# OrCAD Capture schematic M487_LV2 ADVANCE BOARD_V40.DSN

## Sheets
1 EBI_SRAM: size A; title: SRAM; rev: V4.0; note: NuMaker M487 Advance (LV2)
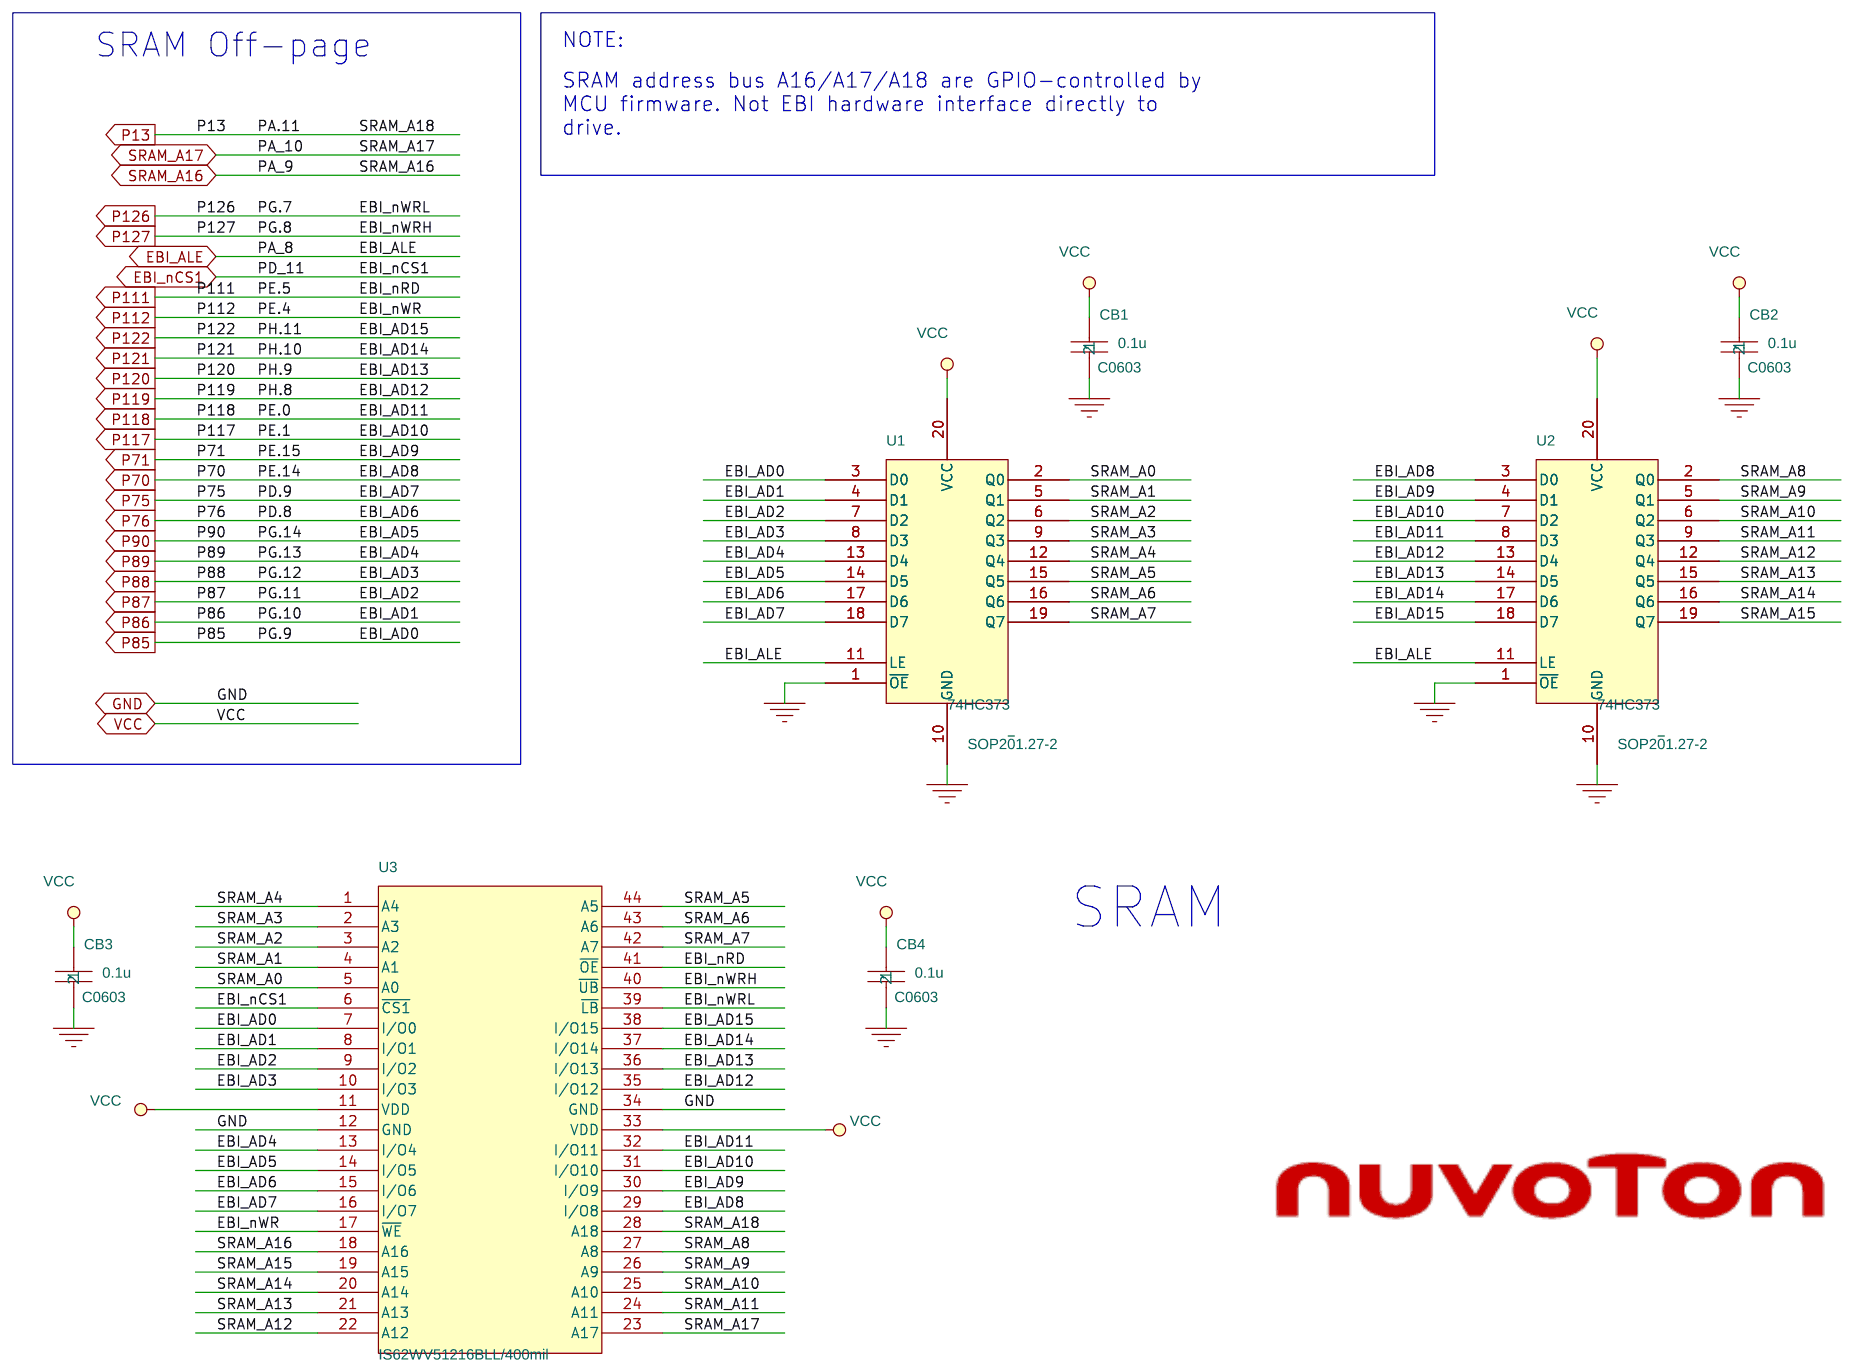
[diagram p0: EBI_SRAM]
2 EBI_TFT LCD: size A4; title: TFT LCD Module
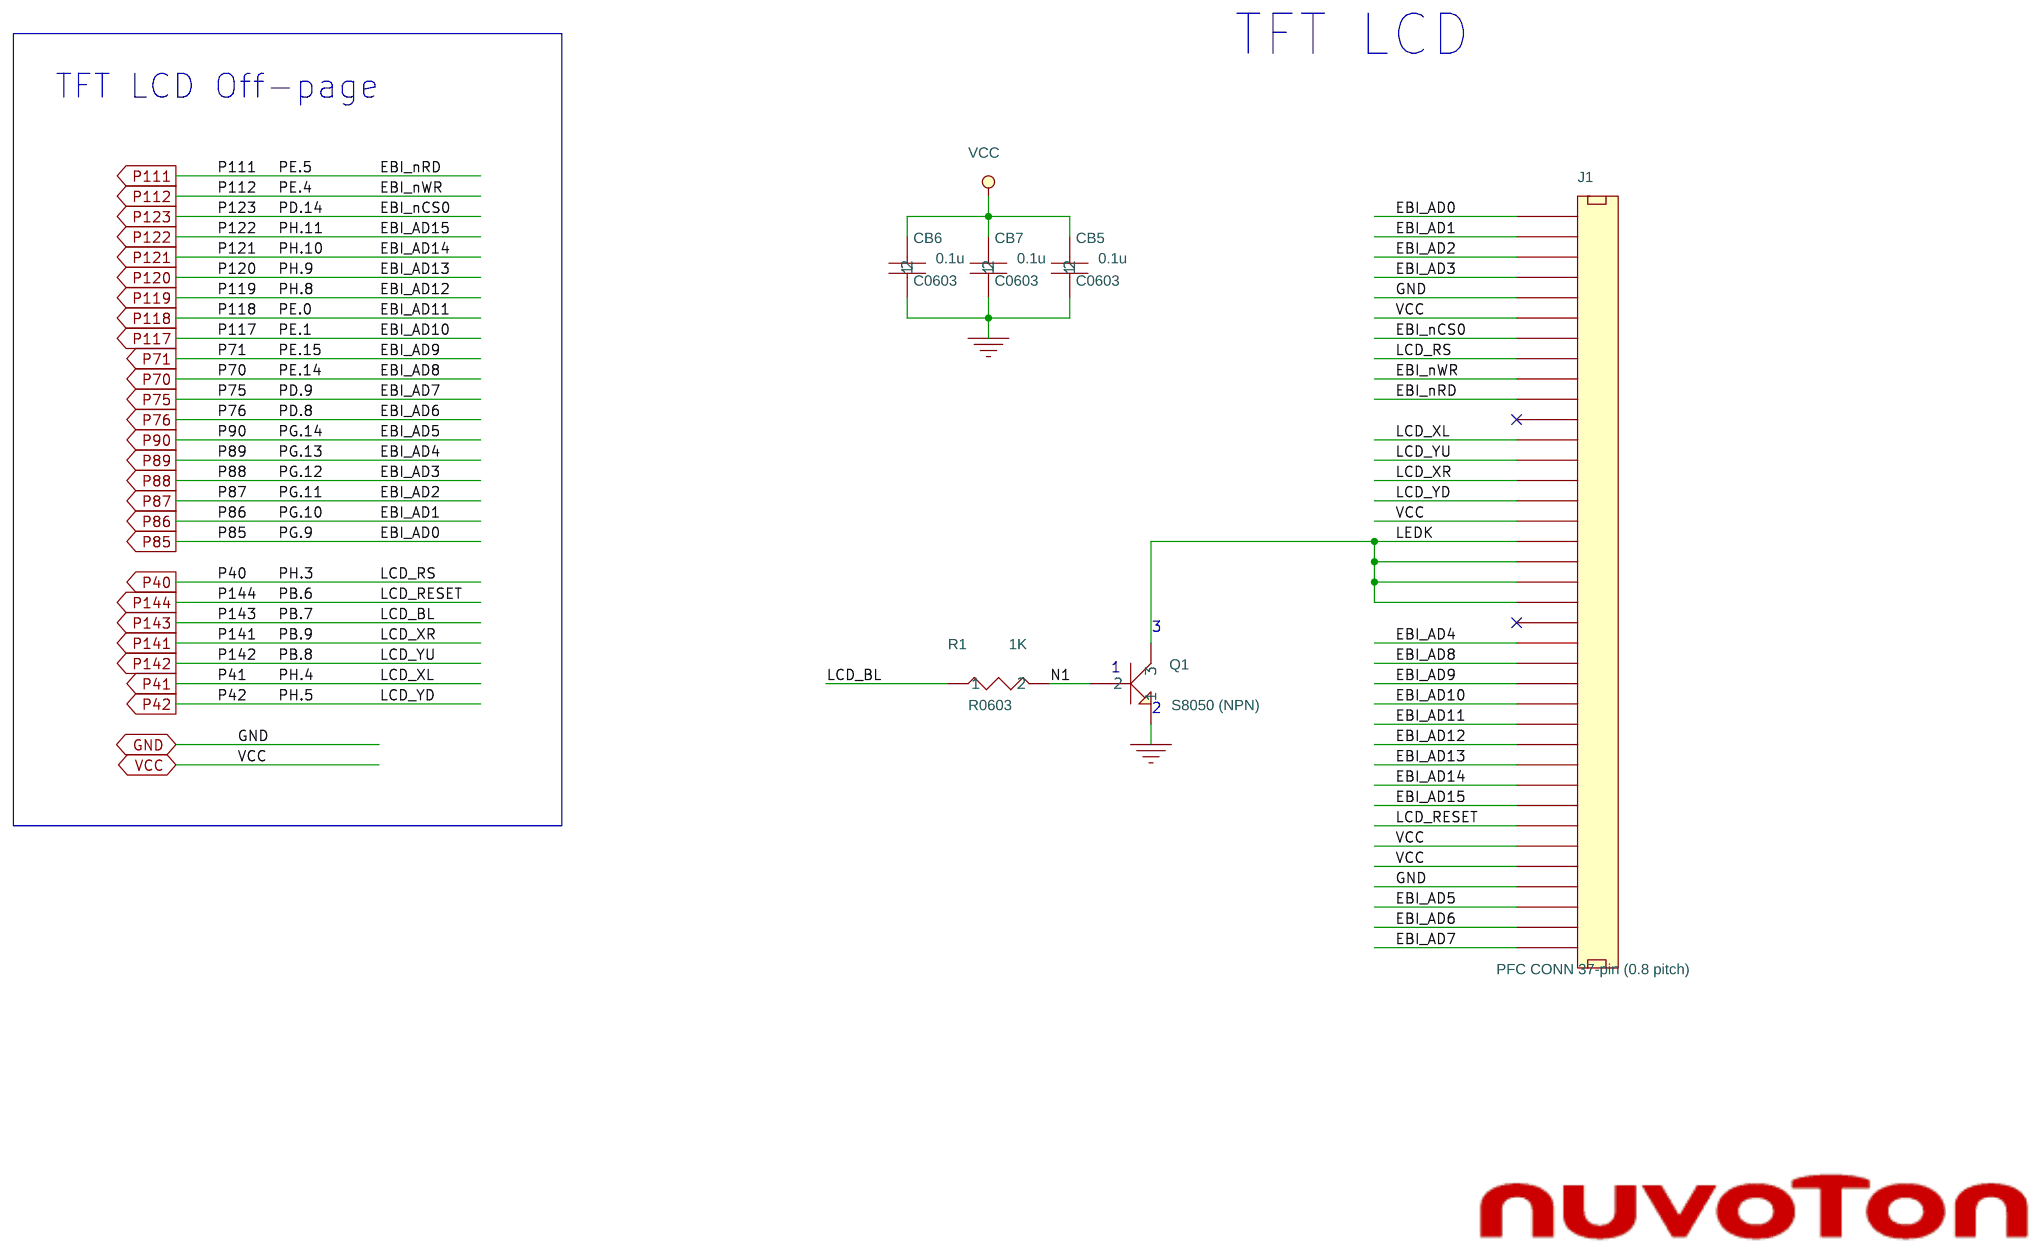
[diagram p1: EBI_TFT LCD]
3 I2C_EEPROM (24LC64): size A; title: I2C EEPROM
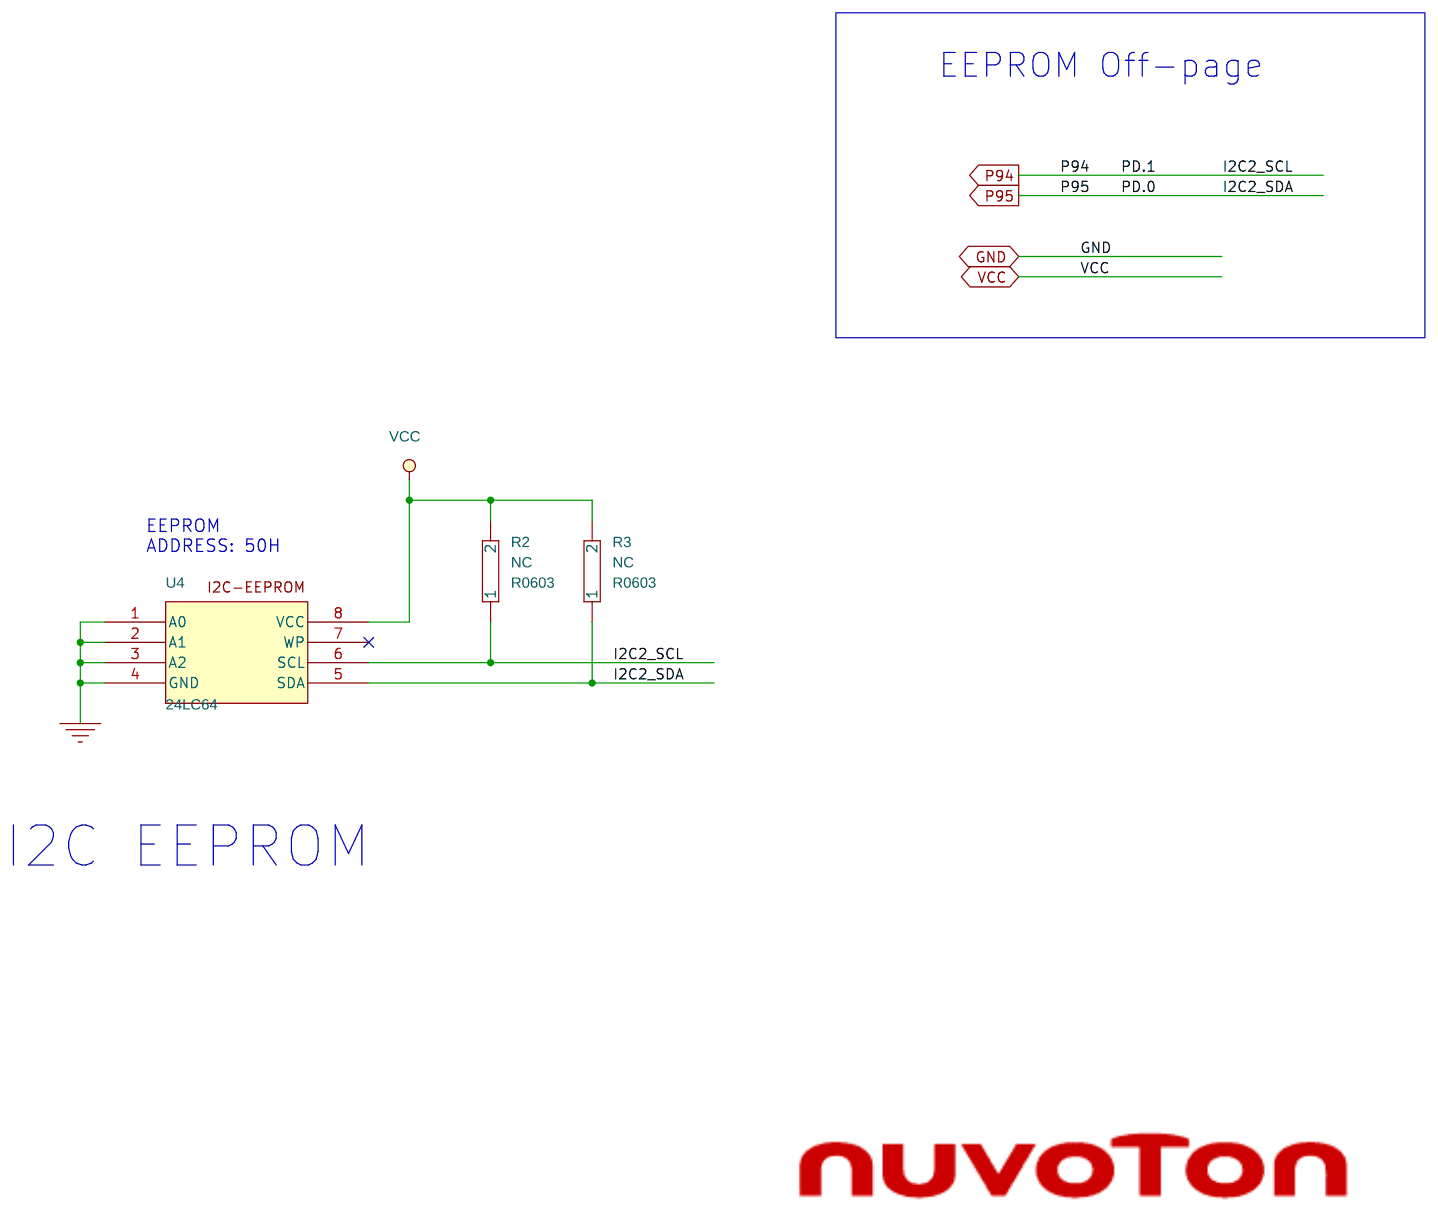
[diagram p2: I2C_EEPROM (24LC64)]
4 I2C_MEMS (MPU6500): size A; title: MEMS (MPU6500)
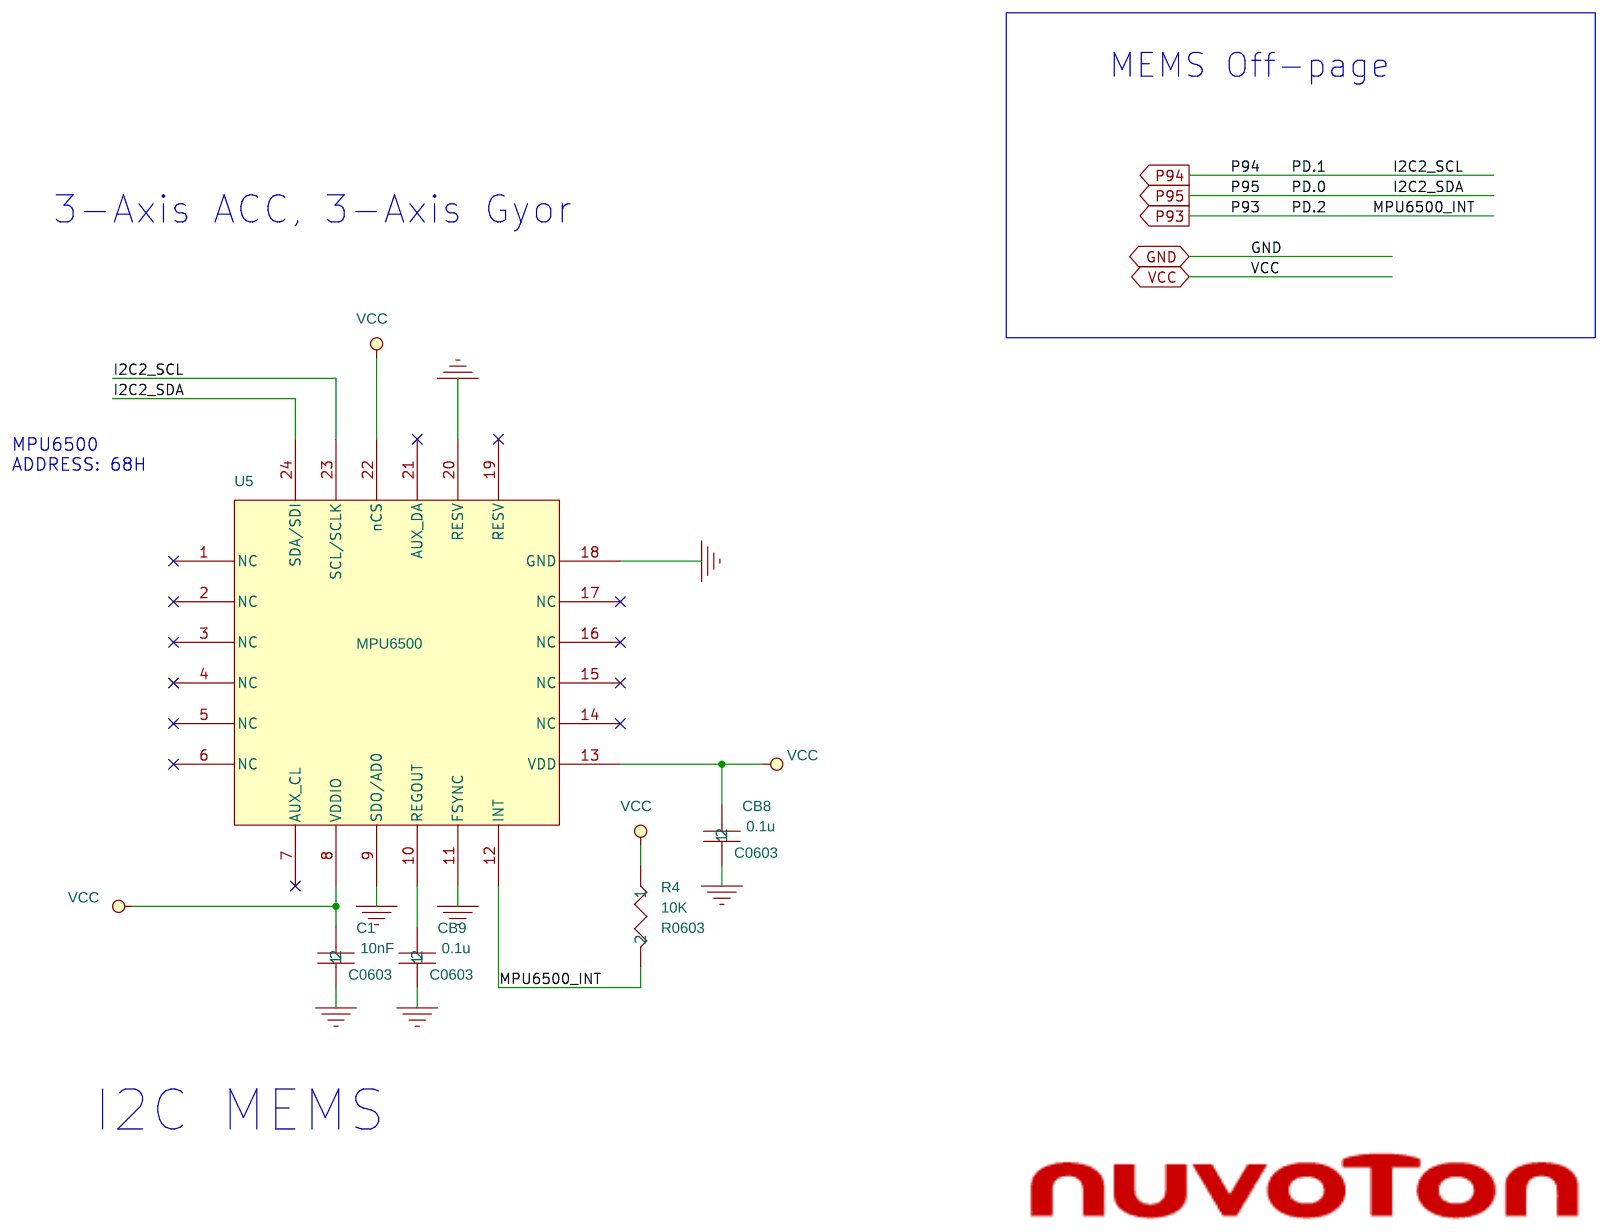
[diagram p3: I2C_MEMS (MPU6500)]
5 Joystick & LED & Keys & Buzzer: size A; title: Joystick, LED, Keys and Buzzer
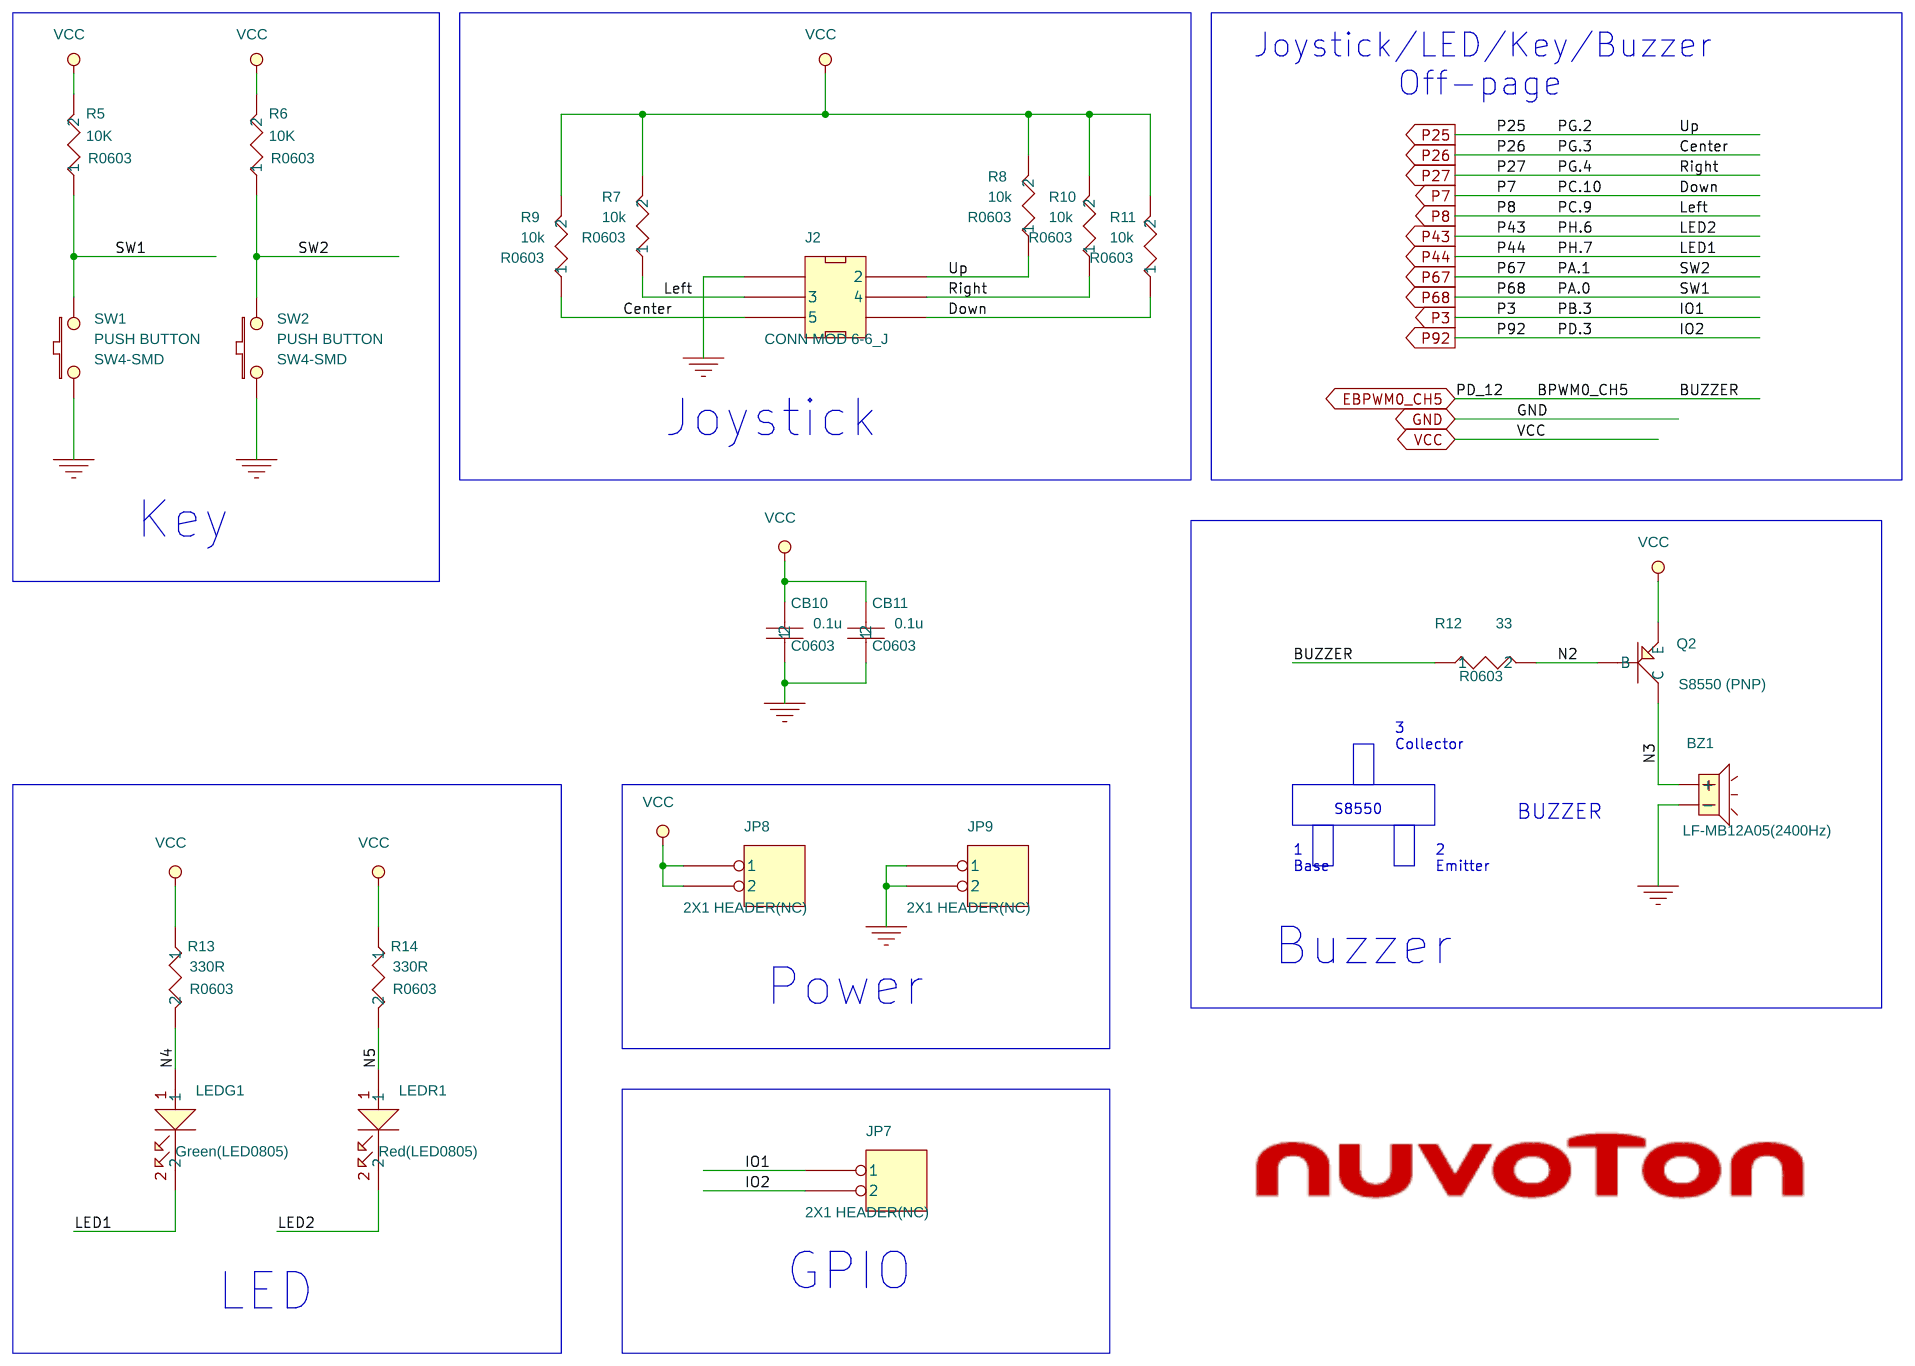
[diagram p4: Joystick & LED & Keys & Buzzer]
6 MCU Connectors: size A4; title: MCU Connectors
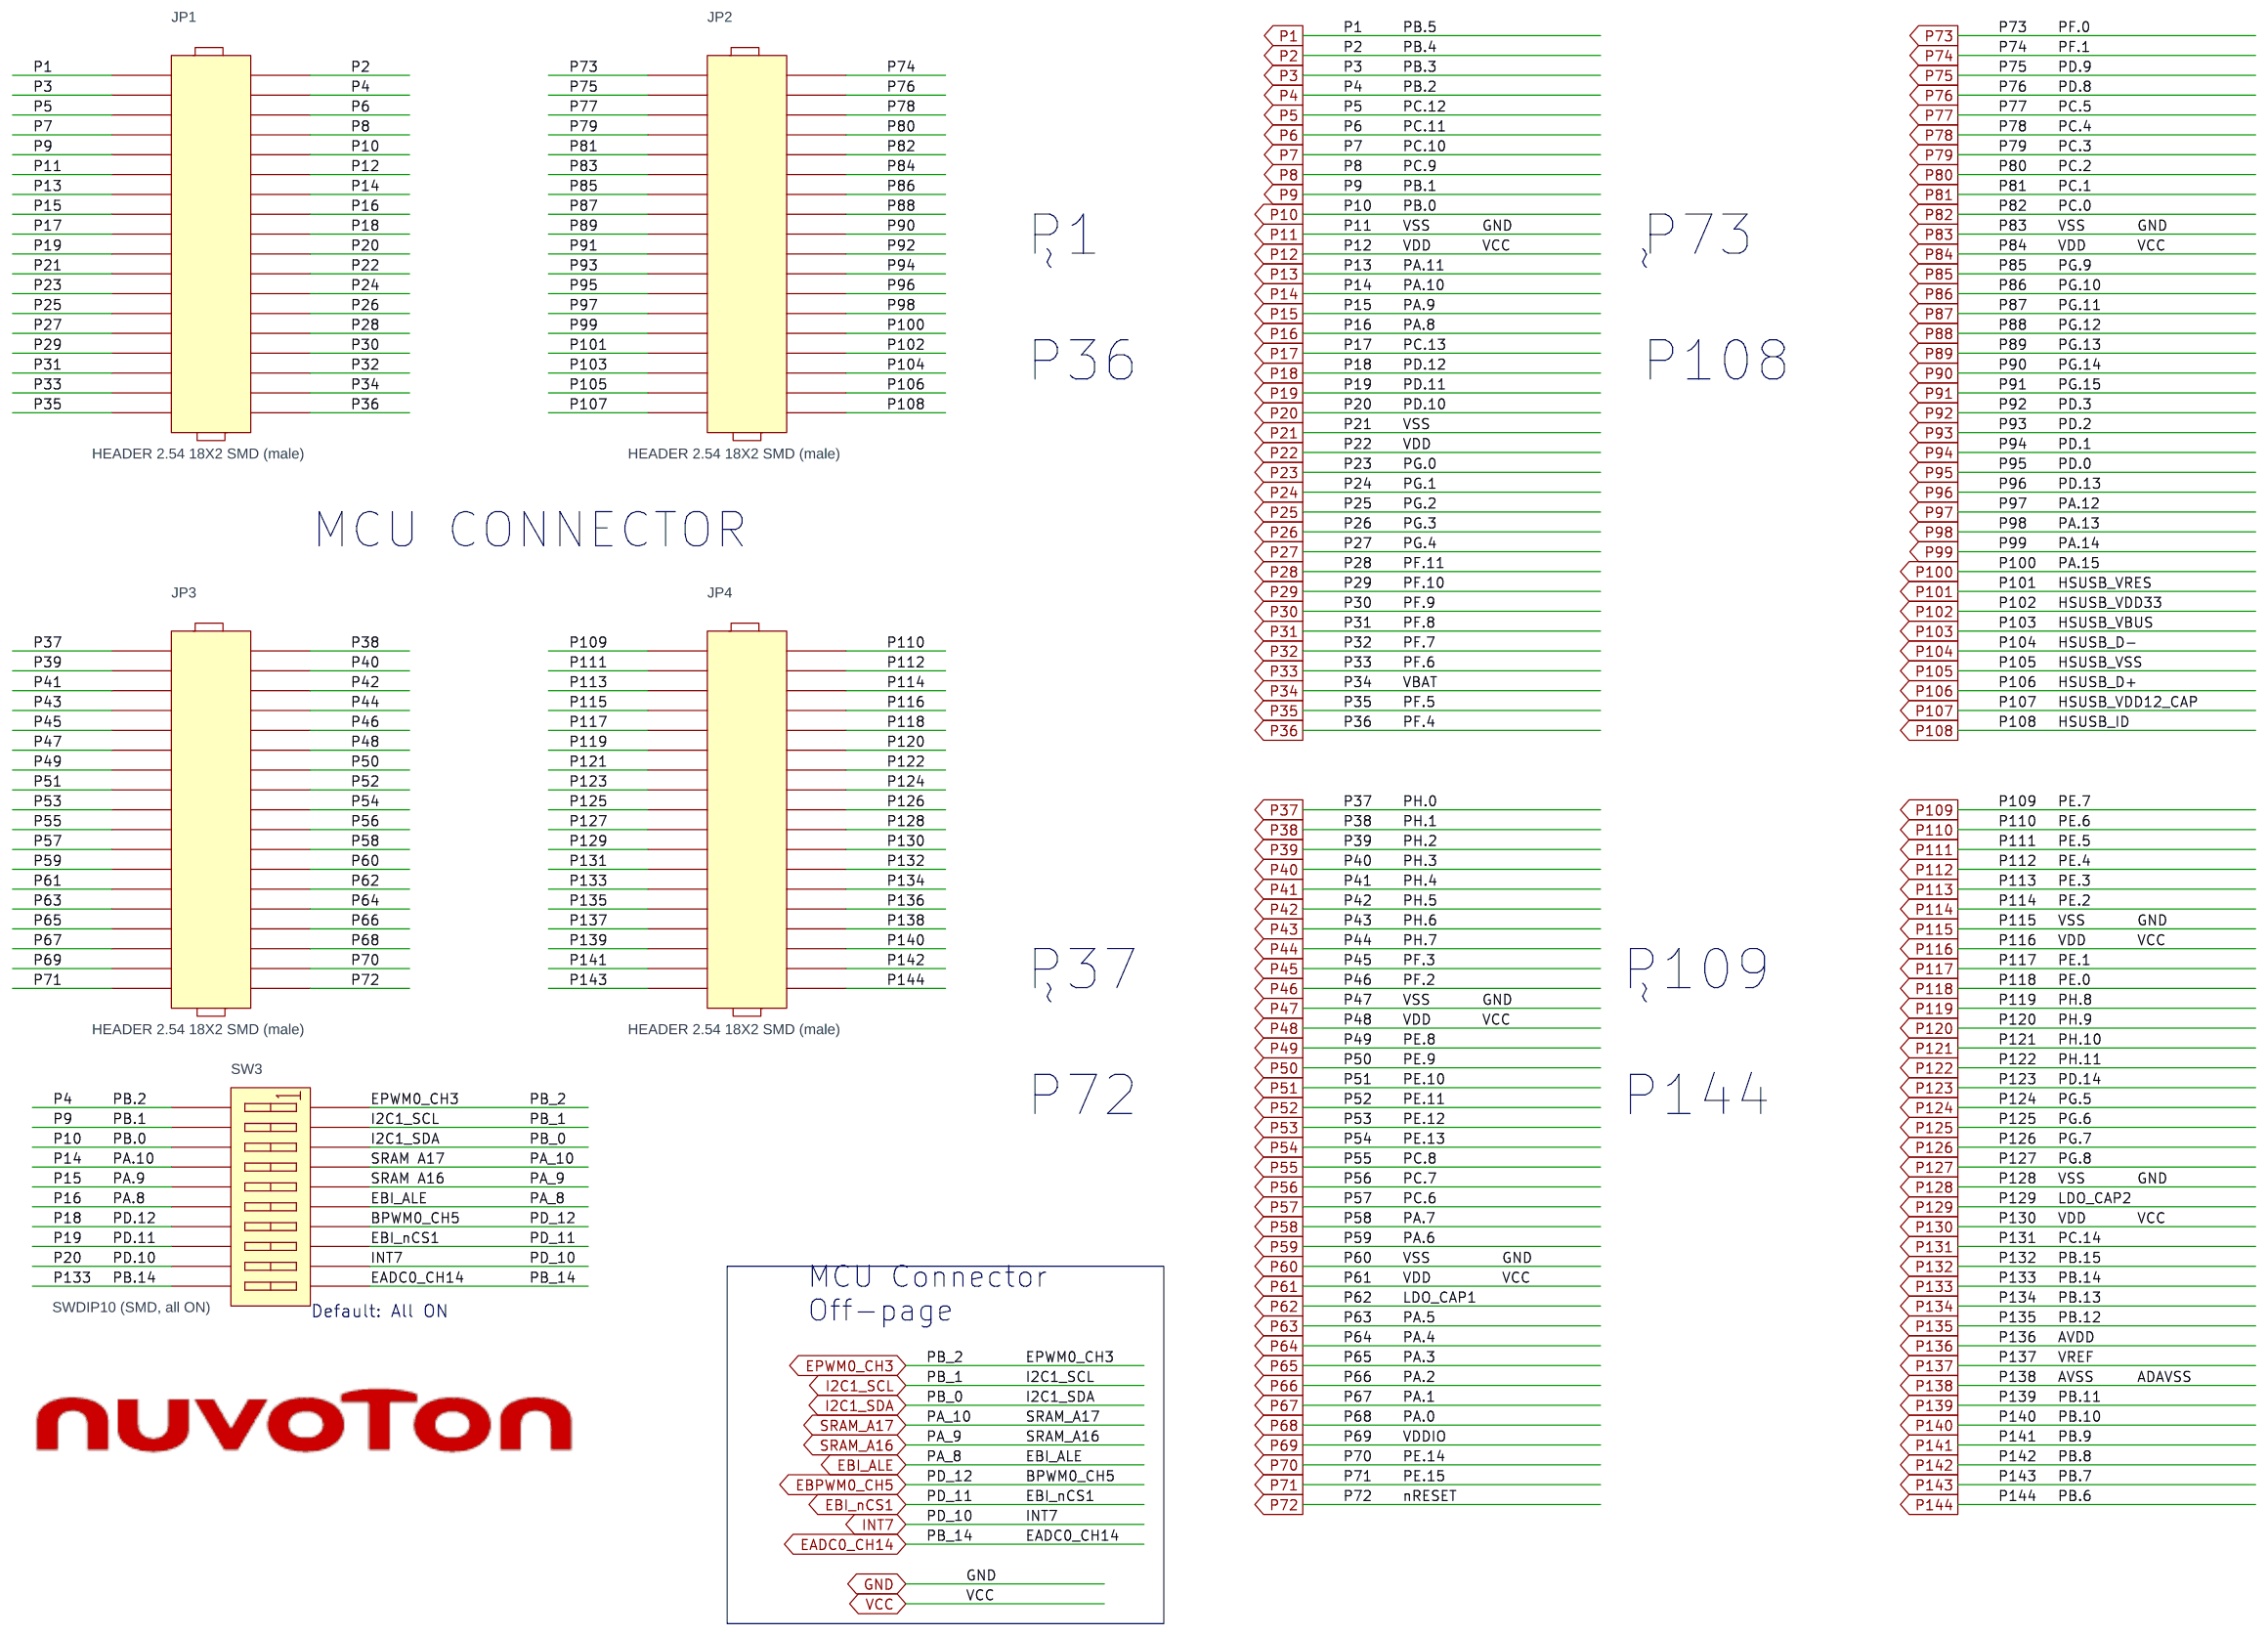
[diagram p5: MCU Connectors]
7 MikroBus: size A; title: Mikro Bus
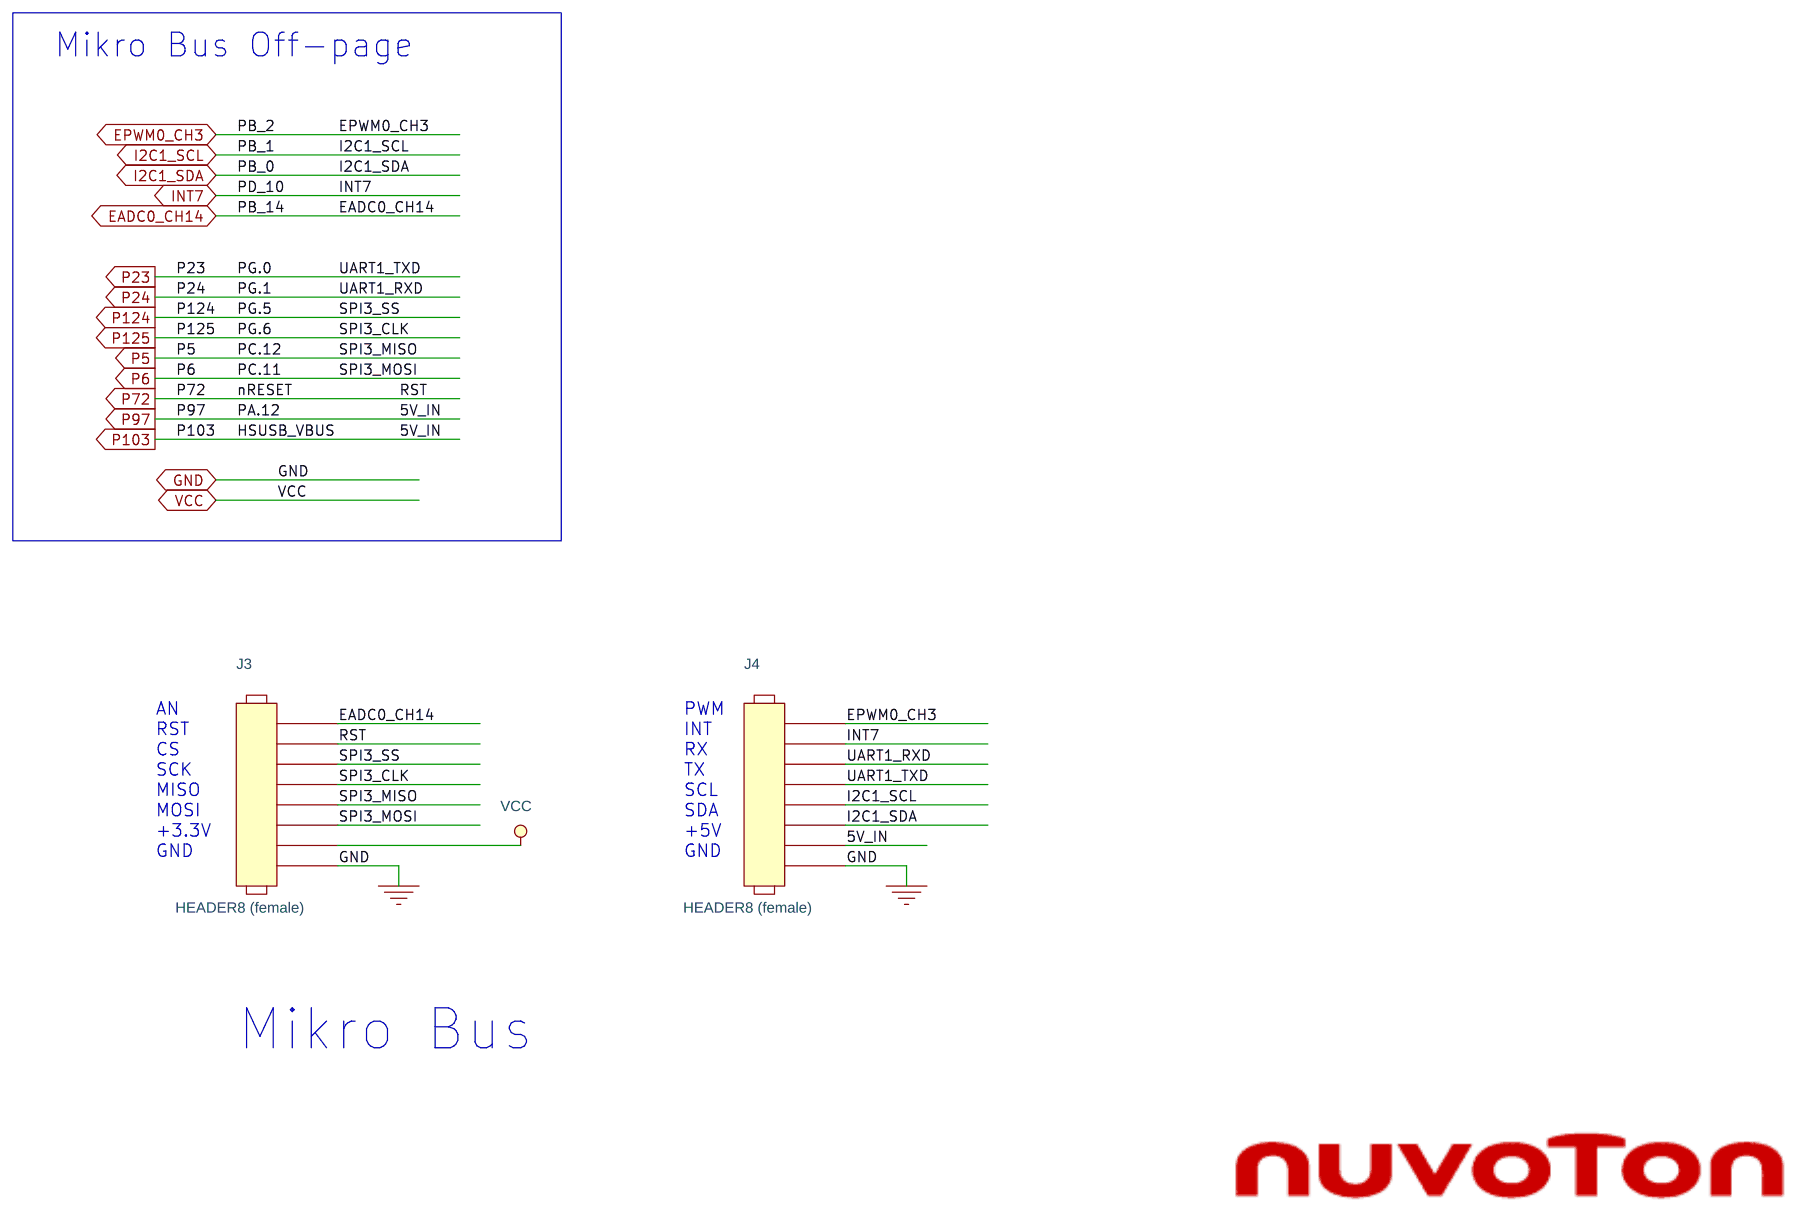
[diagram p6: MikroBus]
8 RS485 and CAN: size A; title: CAN and RS485
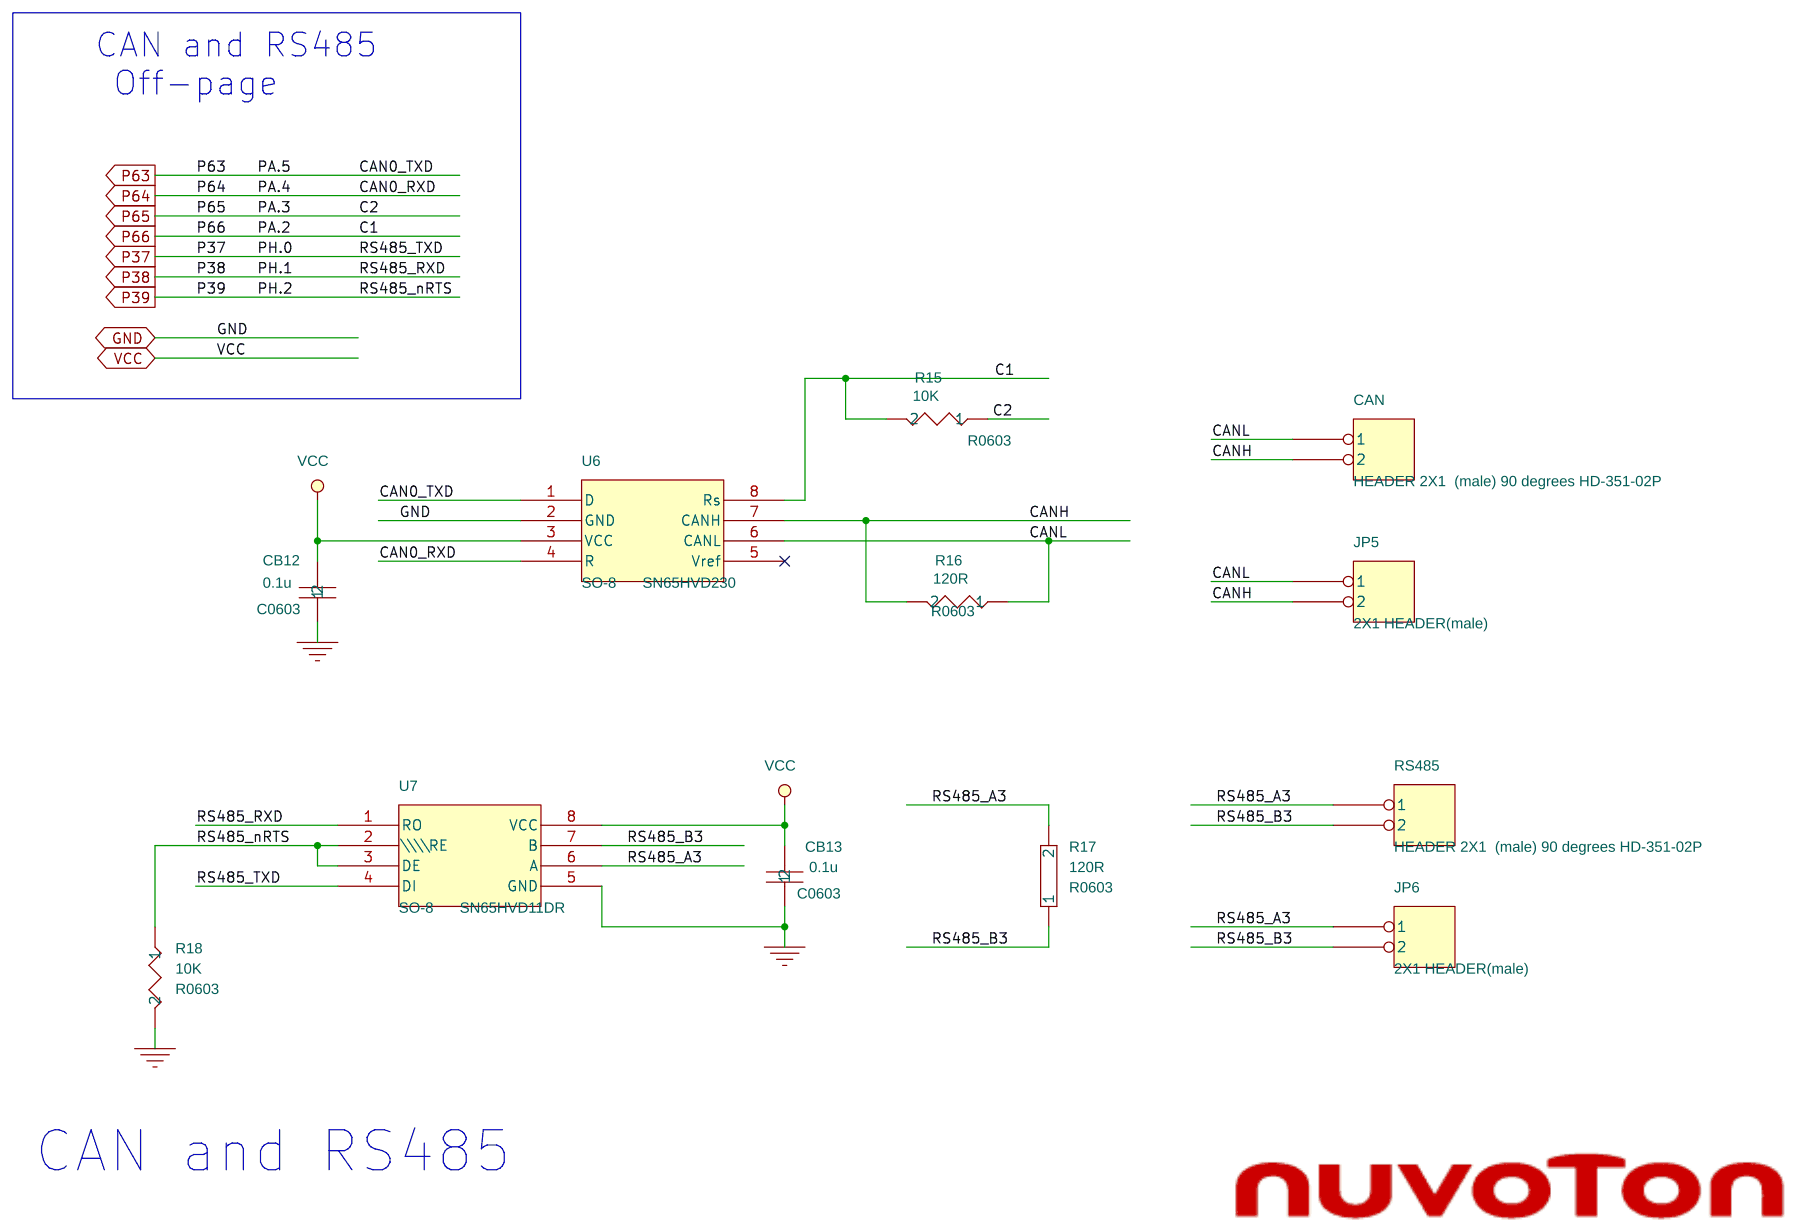
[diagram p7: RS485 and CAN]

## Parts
sheet EBI_SRAM
CB1  0.1u  [C0603]
CB2  0.1u  [C0603]
CB3  0.1u  [C0603]
CB4  0.1u  [C0603]
U1  74HC373  [SOP20\1.27-2]
U2  74HC373  [SOP20\1.27-2]
U3  IS62WV51216BLL/400mil  [TSOP-44(Type II)]
sheet EBI_TFT LCD
CB5  0.1u  [C0603]
CB6  0.1u  [C0603]
CB7  0.1u  [C0603]
J1  PFC CONN 37-pin (0.8 pitch)  [JLT24009C-LCM]
Q1  S8050 (NPN)  [NPN_SOT23]
R1  1K  [R0603]
sheet I2C_EEPROM (24LC64)
R2  NC  [R0603]
R3  NC  [R0603]
U4  24LC64  [SOIC8\1.27\5.6MM]
sheet I2C_MEMS (MPU6500)
C1  10nF  [C0603]
CB8  0.1u  [C0603]
CB9  0.1u  [C0603]
R4  10K  [R0603]
U5  MPU6500  [QFN-24-3X3X0.9MM]
sheet Joystick & LED & Keys & Buzzer
BZ1  LF-MB12A05(2400Hz)  [BUZZER1]
CB10  0.1u  [C0603]
CB11  0.1u  [C0603]
J2  CONN MOD 6-6_J  [Joystick01]
JP7  2X1 HEADER(NC)  [SIP/2P]
JP8  2X1 HEADER(NC)  [SIP/2P]
JP9  2X1 HEADER(NC)  [SIP/2P]
LEDG1  Green(LED0805)  [LED0805]
LEDR1  Red(LED0805)  [LED0805]
Q2  S8550 (PNP)  [SOT-23]
R5  10K  [R0603]
R6  10K  [R0603]
R7  10k  [R0603]
R8  10k  [R0603]
R9  10k  [R0603]
R10  10k  [R0603]
R11  10k  [R0603]
R12  33  [R0603]
R13  330R  [R0603]
R14  330R  [R0603]
SW1  PUSH BUTTON  [SW4-SMD]
SW2  PUSH BUTTON  [SW4-SMD]
sheet MCU Connectors
JP1  HEADER 2.54 18X2 SMD (male)  [HEADER18X2_SMD]
JP2  HEADER 2.54 18X2 SMD (male)  [HEADER18X2_SMD]
JP3  HEADER 2.54 18X2 SMD (male)  [HEADER18X2_SMD]
JP4  HEADER 2.54 18X2 SMD (male)  [HEADER18X2_SMD]
SW3  SWDIP10 (SMD, all ON)  [SWDIP-10\SMD]
sheet MikroBus
J3  HEADER8 (female)  [HEADER8]
J4  HEADER8 (female)  [HEADER8]
sheet RS485 and CAN
CAN  HEADER 2X1  (male) 90 degrees HD-351-02P  [SIP/2P_3.5MM]
CB12  0.1u  [C0603]
CB13  0.1u  [C0603]
JP5  2X1 HEADER(male)  [SIP/2P]
JP6  2X1 HEADER(male)  [SIP/2P]
R15  10K  [R0603]
R16  120R  [R0603]
R17  120R  [R0603]
R18  10K  [R0603]
RS485  HEADER 2X1  (male) 90 degrees HD-351-02P  [SIP/2P_3.5MM]
U6  SN65HVD230  [SO-8]
U7  SN65HVD11DR  [SO-8]

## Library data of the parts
CB1 CB7 CB9 CB10 CB13 = CAP-C_1: Package: 0603
C1 CB2 CB5 = CAP-C_2: Package: 0603
CB3 = CAP-C_3: Package: 0603
CB4 CB6 CB8 CB11 CB12 = CAP-C: Package: 0603
U1 U2 = 74F373_1
U3 = IS62WV51216BLL
J1 = CONN_SOCKET_37
Q1 = NPN
R1 R4 R9 R18 = R_0: Package: 0603
R2 = R_1: Package: 0603
R3 R17 = R: Package: 0603
U4 = M_I2CEEPROM-MC24LC64_1: STUFF_IT: N
U5 = MPU6881
BZ1 = BUZZER: HUA-JIE/PAC-WT-1205-7; Class: DISCRETE; Colay_Alternate: N/A; Colay_Group: N/A; Component_Name: BUZZER/5V 2400HZ 87DB; Critical_Part: N; Data_Sheet: K:\DataSheet\09-INDUCTOR\09G050000400.pdf; Manufacture: HUAJIE; Modify_Data: 2005/5/9; Optional: N/A; Package_Type: DIP; Part Number: 09G050000400; Part Type: 09INDUCTOR\BUZZER; Subsystem_ID: N/A; metal_fabrication: 00000011
J2 = CONN_MOD_6-6_J
JP6 JP7 = HEADER_2_2
CAN JP8 = HEADER_2
JP5 JP9 = HEADER_2_1
LEDG1 = LED_0_1: Package: KP-2012; Vendor: Kingbright
LEDR1 = LED_0: Package: KP-2012; Vendor: Kingbright
Q2 = PNP_2
R5 = R_0_9: Package: 0603
R6 = R_0_6: Package: 0603
R7 = R_0_7: Package: 0603
R8 = R_0_5: Package: 0603
R10 = R_0_4: Package: 0603
R11 = R_0_8: Package: 0603
R12 R16 = R_0_2: Package: 0603
R13 = R_0_3: Package: 0603
R14 R15 = R_0_1: Package: 0603
SW1 SW2 = SW_PUSHBUTTON: Package: DIP PUSH BOTTOM
JP1-JP4 = HEADER_18X2
SW3 = SW_DIP-10_SM
J3 J4 = HEADER_8
RS485 = HEADER_2_3
U6 = SN65HVD230
U7 = ADM232_1: Package: DIP16\SO

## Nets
GND: BZ1.2(-) C1.1 CB1.2 CB2.2 CB3.2 CB4.2 CB5.1 CB6.1 CB7.1 CB8.1 CB9.1 CB10.1 CB11.1 CB12.1 CB13.1 J1.5 J1.34 J2.1 J3.8 J4.8 JP1.11 JP1.21 JP2.11 JP3.11 JP3.24 JP4.7 JP4.20 JP9.1 JP9.2 Q1.1 R18.2 SW1.1 SW2.1 U1.1(~{OE}) U1.10(GND) U2.1(~{OE}) U2.10(GND) U3.12(GND) U3.34(GND) U4.1(A0) U4.2(A1) U4.3(A2) U4.4(GND) U5.9(SDO/AD0) U5.11(FSYNC) U5.18(GND) U5.20(RESV) U6.2(GND) U7.5(GND)
VCC: C1.2 CB1.1 CB2.1 CB3.1 CB4.1 CB5.2 CB6.2 CB7.2 CB8.2 CB10.2 CB11.2 CB12.2 CB13.2 J1.6 J1.16 J1.32 J1.33 J3.7 JP1.12 JP1.22 JP2.12 JP3.12 JP3.25 JP4.8 JP4.22 JP8.1 JP8.2 Q2.2(E) R2.2 R3.2 R4.1 R5.2 R6.2 R7.2 R8.2 R9.2 R10.2 R11.2 R13.1 R14.1 U1.20(VCC) U2.20(VCC) U3.11(VDD) U3.33(VDD) U4.8(VCC) U5.8(VDDIO) U5.13(VDD) U5.22(nCS) U6.3(VCC) U7.8(VCC)
CANH: CAN.2 JP5.2 R16.2 U6.7(CANH)
CANL: CAN.1 JP5.1 R16.1 U6.6(CANL)
EADC0_CH14: J3.1 SW3.11(B10)
EBI_ALE: SW3.15(B6) U1.11(LE) U2.11(LE)
EBI_nCS1: SW3.13(B8) U3.6(~{CS1})
EBPWM0_CH5: R12.1 SW3.14(B7)
EPWM0_CH3: J4.1 SW3.20(B1)
I2C1_SCL: J4.5 SW3.19(B2)
I2C1_SDA: J4.6 SW3.18(B3)
INT7: J4.2 SW3.12(B9)
LEDK: J1.17 J1.18 J1.19 J1.20 Q1.3
N1: Q1.2 R1.2
N2: Q2.1(B) R12.2
N3: BZ1.1(+) Q2.3(C)
N4: LEDG1.1 R13.2
N5: LEDR1.1 R14.2
P1: JP1.1
P2: JP1.2
P3: JP1.3 JP7.1
P4: JP1.4 SW3.1(A1)
P5: J3.5 JP1.5
P6: J3.6 JP1.6
P7: J2.6 JP1.7 R11.1
P8: J2.2(3) JP1.8 R7.1
P9: JP1.9 SW3.2(A2)
P10: JP1.10 SW3.3(A3)
P13: JP1.13 U3.28(A18)
P14: JP1.14 SW3.4(A4)
P15: JP1.15 SW3.5(A5)
P16: JP1.16 SW3.6(A6)
P17: JP1.17
P18: JP1.18 SW3.7(A7)
P19: JP1.19 SW3.8(A8)
P20: JP1.20 SW3.9(A9)
P23: J4.4 JP1.23
P24: J4.3 JP1.24
P25: J2.4(2) JP1.25 R8.1
P26: J2.3(5) JP1.26 R9.1
P27: J2.5(4) JP1.27 R10.1
P28: JP1.28
P29: JP1.29
P30: JP1.30
P31: JP1.31
P32: JP1.32
P33: JP1.33
P34: JP1.34
P35: JP1.35
P36: JP1.36
P37: JP3.1 U7.4(DI)
P38: JP3.2 U7.1(RO)
P39: JP3.3 R18.1 U7.2(\\\\RE) U7.3(DE)
P40: J1.8 JP3.4
P41: J1.12 JP3.5
P42: J1.15 JP3.6
P43: JP3.7 LEDR1.2
P44: JP3.8 LEDG1.2
P45: JP3.9
P46: JP3.10
P49: JP3.13
P50: JP3.14
P51: JP3.15
P52: JP3.16
P53: JP3.17
P54: JP3.18
P55: JP3.19
P56: JP3.20
P57: JP3.21
P58: JP3.22
P59: JP3.23
P62: JP3.26
P63: JP3.27 U6.1(D)
P64: JP3.28 U6.4(R)
P65: JP3.29 R15.1
P66: JP3.30 R15.2 U6.8(Rs)
P67: JP3.31 R6.1 SW2.2
P68: JP3.32 R5.1 SW1.2
P69: JP3.33
P70: J1.23 JP3.34 U2.3(D0) U3.29(I/O8)
P71: J1.24 JP3.35 U2.4(D1) U3.30(I/O9)
P72: J3.2 JP3.36
P73: JP2.1
P74: JP2.2
P75: J1.37 JP2.3 U1.18(D7) U3.16(I/O7)
P76: J1.36 JP2.4 U1.17(D6) U3.15(I/O6)
P77: JP2.5
P78: JP2.6
P79: JP2.7
P80: JP2.8
P81: JP2.9
P82: JP2.10
P85: J1.1 JP2.13 U1.3(D0) U3.7(I/O0)
P86: J1.2 JP2.14 U1.4(D1) U3.8(I/O1)
P87: J1.3 JP2.15 U1.7(D2) U3.9(I/O2)
P88: J1.4 JP2.16 U1.8(D3) U3.10(I/O3)
P89: J1.22 JP2.17 U1.13(D4) U3.13(I/O4)
P90: J1.35 JP2.18 U1.14(D5) U3.14(I/O5)
P91: JP2.19
P92: JP2.20 JP7.2
P93: JP2.21 R4.2 U5.12(INT)
P94: JP2.22 R2.1 U4.6(SCL) U5.23(SCL/SCLK)
P95: JP2.23 R3.1 U4.5(SDA) U5.24(SDA/SDI)
P96: JP2.24
P98: JP2.26
P99: JP2.27
P100: JP2.28
P101: JP2.29
P102: JP2.30
P103: J4.7 JP2.25 JP2.31
P104: JP2.32
P105: JP2.33
P106: JP2.34
P107: JP2.35
P108: JP2.36
P109: JP4.1
P110: JP4.2
P111: J1.10 JP4.3 U3.41(~{OE})
P112: J1.9 JP4.4 U3.17(~{WE})
P113: JP4.5
P114: JP4.6
P117: J1.25 JP4.9 U2.7(D2) U3.31(I/O10)
P118: J1.26 JP4.10 U2.8(D3) U3.32(I/O11)
P119: J1.27 JP4.11 U2.13(D4) U3.35(I/O12)
P120: J1.28 JP4.12 U2.14(D5) U3.36(I/O13)
P121: J1.29 JP4.13 U2.17(D6) U3.37(I/O14)
P122: J1.30 JP4.14 U2.18(D7) U3.38(I/O15)
P123: J1.7 JP4.15
P124: J3.3 JP4.16
P125: J3.4 JP4.17
P126: JP4.18 U3.39(~{LB})
P127: JP4.19 U3.40(~{UB})
P129: JP4.21
P131: JP4.23
P132: JP4.24
P133: JP4.25 SW3.10(A10)
P134: JP4.26
P135: JP4.27
P136: JP4.28
P137: JP4.29
P138: JP4.30
P139: JP4.31
P140: JP4.32
P141: J1.14 JP4.33
P142: J1.13 JP4.34
P143: JP4.35 R1.1
P144: J1.31 JP4.36
RS485_A3: JP6.1 R17.2 RS485.1 U7.6(A)
RS485_B3: JP6.2 R17.1 RS485.2 U7.7(B)
SRAM_A0: U1.2(Q0) U3.5(A0)
SRAM_A1: U1.5(Q1) U3.4(A1)
SRAM_A2: U1.6(Q2) U3.3(A2)
SRAM_A3: U1.9(Q3) U3.2(A3)
SRAM_A4: U1.12(Q4) U3.1(A4)
SRAM_A5: U1.15(Q5) U3.44(A5)
SRAM_A6: U1.16(Q6) U3.43(A6)
SRAM_A7: U1.19(Q7) U3.42(A7)
SRAM_A8: U2.2(Q0) U3.27(A8)
SRAM_A9: U2.5(Q1) U3.26(A9)
SRAM_A10: U2.6(Q2) U3.25(A10)
SRAM_A11: U2.9(Q3) U3.24(A11)
SRAM_A12: U2.12(Q4) U3.22(A12)
SRAM_A13: U2.15(Q5) U3.21(A13)
SRAM_A14: U2.16(Q6) U3.20(A14)
SRAM_A15: U2.19(Q7) U3.19(A15)
SRAM_A16: SW3.16(B5) U3.18(A16)
SRAM_A17: SW3.17(B4) U3.23(A17)
N20210190: CB9.2 U5.10(REGOUT)

Not connected (* = marked no-connect by the designer): J1 11* 21*; U4 7(WP)*; U5 1(NC)* 2(NC)* 3(NC)* 4(NC)* 5(NC)* 6(NC)* 7(AUX_CL)* 14(NC)* 15(NC)* 16(NC)* 17(NC)* 19(RESV)* 21(AUX_DA)*; U6 5(Vref)*

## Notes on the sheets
sheet 1
- SRAM Off-page
- NOTE:
- SRAM address bus A16/A17/A18 are GPIO-controlled by
  MCU firmware. Not EBI hardware interface directly to
  drive.
- SRAM
sheet 2
- TFT LCD
- TFT LCD Off-page
- 3
- 1
- 2
sheet 3
- EEPROM Off-page
- EEPROM
  ADDRESS: 50H
- I2C EEPROM
sheet 4
- MEMS Off-page
- 3-Axis ACC, 3-Axis Gyor
- MPU6500
  ADDRESS: 68H
- I2C MEMS
sheet 5
- Joystick/LED/Key/Buzzer
          Off-page
- Joystick
- Key
- 3
  Collector
- S8550
- BUZZER
- 1
  Base
- 2
  Emitter
- Buzzer
- Power
- GPIO
- LED
sheet 6
- P1
  P36
- P73
  P108
- ~
- ~
- MCU CONNECTOR
- P37
  P72
- P109
  P144
- ~
- ~
- MCU Connector
  Off-page
- Default: All ON
sheet 7
- Mikro Bus Off-page
- AN
- PWM
- RST
- INT
- CS
- SCK
- RX
- TX
- MISO
- SCL
- MOSI
- SDA
- +3.3V
- +5V
- GND
- GND
- Mikro Bus
sheet 8
- CAN and RS485
   Off-page
- CAN and RS485
